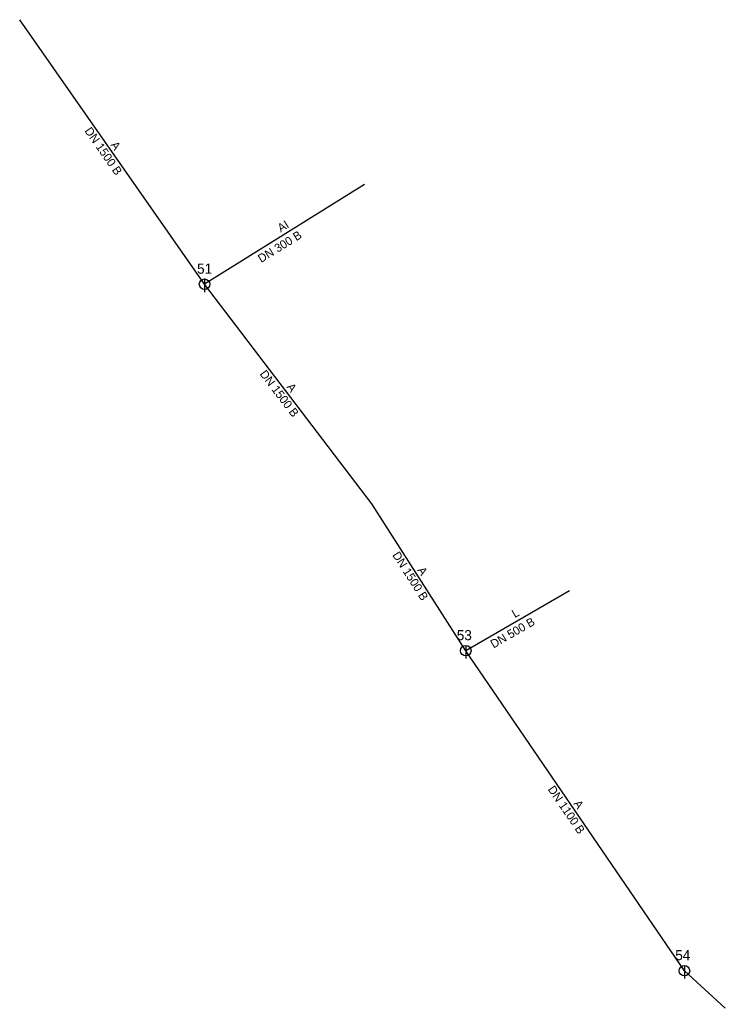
# Model space of a CAD drawing. Extents: x -451228 to -451094, y -1101872 to -1101684.
import ezdxf

# ---------------------------------------------------------------- set-up
doc = ezdxf.new("R2010")
doc.units = 0
for name, color, linetype in [('_stoka_jednotna_smvak_prevzato_z_dokumentace_', 7, 'Continuous'), ('Default', 7, 'Continuous'), ('MoLevel 119', 7, 'Continuous'), ('MoLevel 120', 7, 'Continuous'), ('MoLevel 68', 7, 'Continuous'), ('MoLevel 69', 7, 'Continuous')]:
    doc.layers.add(name, color=color, linetype=linetype)

# ---------------------------------------------------------------- blocks, each defined once
blk = doc.blocks.new('_sachta_kanal_prevzato_z_dokumentace_')
at = {"layer": 'Default'}
blk.add_line((0, 0.00005), (0, -0.000075), dxfattribs=at)
blk.add_circle((0, 0), 0.00005, dxfattribs=at)

msp = doc.modelspace()

# ---------------------------------------------------------------- linework, layer by layer
at = {"layer": '_stoka_jednotna_smvak_prevzato_z_dokumentace_'}
for p, q in [((-451193.17, -1101734.02), (-451228.34, -1101683.69)), ((-451162.72, -1101715.07), (-451193.17, -1101734.02)), ((-451161.3, -1101775.8), (-451193.17, -1101734.02)), ((-451143.45, -1101803.76), (-451161.3, -1101775.8)), ((-451123.71, -1101792.36), (-451143.45, -1101803.76)), ((-451101.83, -1101864.66), (-451143.45, -1101803.76)), ((-451094.06, -1101871.8), (-451101.83, -1101864.66))]:
    msp.add_line(p, q, dxfattribs=at)

# ---------------------------------------------------------------- block references
at = {"layer": 'MoLevel 119', "xscale": 20000, "yscale": 20000}
for p in [(-451193.17, -1101734.02), (-451143.45, -1101803.76), (-451101.83, -1101864.66)]:
    msp.add_blockref('_sachta_kanal_prevzato_z_dokumentace_', p, dxfattribs=at)

# ---------------------------------------------------------------- texts
at = {"layer": 'MoLevel 120'}
for s, p in [('51', (-451194.59, -1101732.02)), ('53', (-451145.15, -1101801.76)), ('54', (-451103.57, -1101862.66))]:
    msp.add_text(s, height=1.926, dxfattribs=at).set_placement(p)
at = {"layer": 'MoLevel 68'}
for s, rotation, p in [('DN 1500 B', 304.9454, (-451216.08, -1101704.84)), ('DN 300 B', 31.8953, (-451182.39, -1101730)), ('DN 1500 B', 307.3366, (-451182.75, -1101751.12)), ('DN 1500 B', 302.5547, (-451157.49, -1101785.55)), ('DN 500 B', 30.0068, (-451138.17, -1101803.36)), ('DN 1100 B', 304.3493, (-451127.91, -1101830.14))]:
    msp.add_text(s, height=1.605, rotation=rotation, dxfattribs=at).set_placement(p)
at = {"layer": 'MoLevel 69'}
for s, height, rotation, p in [('A', 1.6, 304.9454, (-451211.13, -1101707.52)), ('AI', 1.605, 31.8953, (-451178.66, -1101724.19)), ('A', 1.6, 307.3366, (-451177.63, -1101753.59)), ('A', 1.6, 302.5547, (-451152.72, -1101788.43)), ('L', 1.6, 30.0068, (-451134.11, -1101797.57)), ('A', 1.6, 304.3493, (-451123.01, -1101832.87))]:
    msp.add_text(s, height=height, rotation=rotation, dxfattribs=at).set_placement(p)

doc.saveas('drawing.dxf')
